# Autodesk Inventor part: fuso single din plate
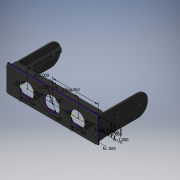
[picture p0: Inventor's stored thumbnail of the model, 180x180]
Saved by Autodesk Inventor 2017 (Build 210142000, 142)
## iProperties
Created: 2017-04
Part Number: fuso single din plate
Material: PET Plastic
Document SubType Name: Modeling
Designer: Jon Turner
Density: 1.541 g/cm^3
Appearance: Rubber - Black
Author: Jon Turner
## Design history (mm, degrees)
sketch "Sketch1"
  geometry: L1 (0, 0)-(180.975, 0); L2 (180.975, 0)-(180.975, 50.8); L3 (180.975, 50.8)-(0, 50.8); L4 (0, 50.8)-(0, 0); L5 (25.424, 29.564)-(25.424, 21.236); L6 (53.951, 21.236)-(53.951, 29.564); L7 (53.951, 29.564)-(25.424, 21.236); L8 (53.951, 21.236)-(25.424, 29.564); L9 (127.024, 29.564)-(127.024, 21.236); L10 (155.551, 21.236)-(155.551, 29.564); L11 (155.551, 29.564)-(127.024, 21.236); L12 (155.551, 21.236)-(127.024, 29.564); C1 r 15.684 at (90.487, 25.4); A1 r 14.859 centre (39.688, 25.4) between (25.424, 21.236) and (53.951, 21.236); A2 r 14.859 centre (39.688, 25.4) between (53.951, 29.564) and (25.424, 29.564); A3 r 14.859 centre (141.287, 25.4) between (127.024, 21.236) and (155.551, 21.236); A4 r 14.859 centre (141.287, 25.4) between (155.551, 29.564) and (127.024, 29.564)
  constraints: 24 end point, 8 point on circle, 5 centre point, 4 parallel, 1 horizontal, 1 perpendicular
  dimensions: "d0" = 180.975 distance of L3.end L2.end; "d1" = 50.8 distance of L2.end L1.end; "d39" = 31.369 diameter of C1; "d58" = 25.4 distance from line of L3 C1.centre (= d57); "d62" = 90.4875 distance from line of L2 C1.centre (= 0.5 x d0); "d64" = 14.859 radius of A2 (= d65); "d65" = 14.859 radius of A1; "d66" = 8.32795 distance of L5.start L5.end; "d67" = 8.32795 distance of L6.start L6.end; "d69" = 28.52726 distance between parallel lines of L5 L6 (derived); "d70" = 14.859 radius of A4 (= d71); "d71" = 14.859 radius of A3 (= d65); "d72" = 8.32795 distance of L9.start L9.end; "d73" = 8.32795 distance of L10.start L10.end; "d74" = 28.52726 distance between parallel lines of L9 L10 (derived); "d75" = 50.8 distance of C1.centre A3.centre; "d76" = 50.8 distance of C1.centre A1.centre (= d75); "d77" = 25.4 distance from line of L3 A3.centre (= d58); "d78" = 25.4 distance from line of L3 A1.centre (= d58)
extrude "Extrusion1" new body sketch "Sketch1" distance "d2" = 2; taper "d3" = 0 deg
sketch "Sketch2"
  geometry: L1 (-4.381, 46.583)-(-2.381, 46.583); L2 (-2.381, 46.583)-(-2.381, 3.583); L3 (-2.381, 3.583)-(-4.381, 3.583); L4 (-178.594, 46.583)-(-176.594, 46.583); L5 (-176.594, 3.583)-(-178.594, 3.583); L6 (-178.594, 3.583)-(-178.594, 46.583); L7 (0, 50.8)-(0, 0) reference; L8 (-180.975, 0)-(-180.975, 50.8) reference; L9 (-6.381, 28.945)-(-6.381, 28.945); L10 (-6.381, 28.945)-(-6.381, 21.22); L11 (-6.381, 21.22)-(-6.381, 21.22); L12 (-6.381, 25.083)-(-4.381, 25.083); L13 (-2.381, 25.083)-(-4.381, 25.083); L14 (-180.975, 50.8)-(0, 50.8) reference; L15 (-90.487, 50.8)-(-90.487, 0); L16 (-174.594, 28.945)-(-174.594, 21.22); L17 (-174.594, 28.945)-(-174.594, 28.945); L18 (-174.594, 25.083)-(-176.594, 25.083); L19 (-174.594, 21.22)-(-174.594, 21.22); L20 (-4.381, 3.583)-(-4.381, 19.22); L21 (-4.381, 30.945)-(-4.381, 46.583); L22 (-176.594, 46.583)-(-176.594, 30.945); L23 (-176.594, 19.22)-(-176.594, 3.583); L24 (-176.594, 30.945)-(-174.594, 28.945); L25 (-176.594, 19.22)-(-174.594, 21.22); L26 (-6.381, 28.945)-(-4.381, 30.945); L27 (-6.381, 21.22)-(-4.381, 19.22); 4 further points
  constraints: 48 end point, 10 point on line, 7 parallel, 7 symmetric about line, 4 perpendicular, 3 horizontal, 3 midpoint, 1 collinear, 1 vertical
  dimensions: "d4" = 2.38125 distance between parallel lines of L7 L2; "d5" = 2.38125 distance between parallel lines of L6 L8 (= d4); "d8" = 43 distance from line of L5.start L4; "d28" = 2 distance of point (-4.381, 28.945) L9.end (= d7); "d29" = 2 distance of L1.start L1.end; "d30" = 2 distance of L22.end point (-176.594, 28.945) (= d29); "d31" = 2 distance of L17.start point (-176.594, 28.945) (= d30); "d32" = 2 distance of L23.start point (-176.594, 21.22) (= d30); "d33" = 2 distance of L19.end point (-176.594, 21.22) (= d32); "d34" = 2 distance of L9.start point (-4.381, 28.945) (= d30); "d35" = 2 distance of L21.start point (-4.381, 28.945) (= d34); "d36" = 2 distance of L11.end point (-4.381, 21.22) (= d30); "d37" = 2 distance of L20.end point (-4.381, 21.22) (= d36)
extrude "Extrusion2" join sketch "Sketch2" distance "d9" = 101.6; taper "d10" = 0 deg
sketch "Sketch3"
  geometry: L1 (2, 47.217)-(2, -3.583) reference; C1 r 2.25 at (-42.018, 21.649); C2 r 2.25 at (-86.036, 21.817); 1 further point
  constraints: 2 centre point, 1 equal radius
  dimensions: "d20" = 4.5 diameter of C1; "d21" = 44.0182 distance from line of L1 C1.centre; "d22" = 44.0182 horizontal distance of C1.centre C2.centre (= d21)
extrude "Extrusion3" cut sketch "Sketch3" stored distance "d23" = 101.6; taper "d24" = 0 deg
fillet "Fillet1" dims "d25" = 20.32
fillet "Fillet3" dims "d27" = 3.175
extrude "Extrusion4" cut sketch "Sketch1" stored distance "d79" = 101.6; taper "d80" = 0 deg
sketch "Sketch4"
  geometry: L1 (-178.594, 49.758)-(-178.594, 46.583) reference; L2 (-2.381, 46.583)-(-2.381, 3.583) reference; L3 (-178.594, 49.758)-(-2.381, 49.758); L4 (-2.381, 49.758)-(-2.381, 0.408); L5 (-2.381, 0.408)-(-178.594, 0.408); L6 (-178.594, 0.408)-(-178.594, 49.758); L7 (-4.381, 3.583)-(-7.556, 0.408) reference; L8 (-175.517, 48.258)-(-6.056, 48.258); L9 (-6.056, 48.258)-(-6.056, 1.908); L10 (-6.056, 1.908)-(-175.517, 1.908); L11 (-175.517, 1.908)-(-175.517, 48.258); 2 further points
  constraints: 16 end point, 4 parallel, 2 horizontal, 2 perpendicular, 1 point on line
  dimensions: "d81" = 1.5 distance between parallel lines of L8 L3 (= d82); "d82" = 1.5 distance between parallel lines of L5 L10
extrude "Extrusion5" join sketch "Sketch4" distance "d83" = 12.7; taper "d84" = 0 deg
fillet "Fillet5" dims "d85" = 3.175
fillet "Fillet6" dims "d86" = 3.175
body "Solid1"
other parameters: "d6" = 2, "d7" = 2 (= d6), "d45" = 31.369 (= d39), "d57" = 25.4 (= 0.5 x d1), "d68" = 14.605, "sa_0" = 9809.988, "sa_1" = 0, "sa_2" = 0, "sa_3" = -88964.43231
